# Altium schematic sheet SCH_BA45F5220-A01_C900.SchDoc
size A4; PageSetup: Record=PageOptions¦CenterHorizontal=True¦CenterVertical=True¦PrintScale=1.00¦XCorrection=1.00¦YCorrection=1.00¦PrintKind=1¦BorderSize=5000000¦LeftOffset=0¦BottomOffset=0¦Orientation=2¦PaperLength=1000¦PaperWidth=1000¦Scale=100¦PaperSource=7¦PrintQuality=-4¦MediaType=1¦DitherType=10¦PaperKind=A4¦PrintScaleMode=0
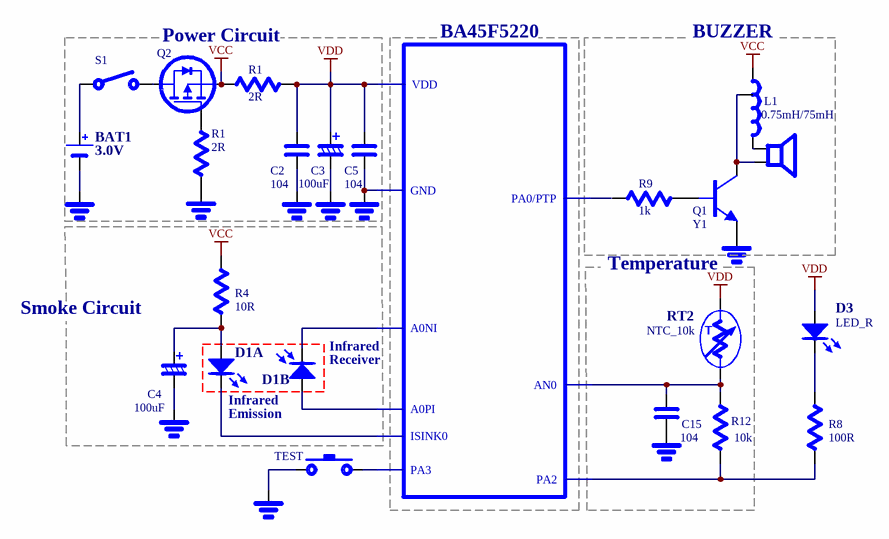
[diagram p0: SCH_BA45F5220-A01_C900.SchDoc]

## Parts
(Parts that share a designator on the sheet are numbered #1, #2 ... from top to bottom, then left to right.)
*  *  (value not drawn)
BAT1  3.0V  [CR2032]
C2  104
C3  100uF
C4  100uF
C5  104
C15  104
D1A  LED(1)  [LED3M]  (value not drawn)
D1B  *  [LED3M]  (value not drawn)
D3  LED_R  [LED3M]
GND1  GND(1)  (value not drawn)
GND2#1  GND(1)  (value not drawn)
GND2#2  GND(1)  (value not drawn)
GND2#3  GND(1)  (value not drawn)
GND3  GND(1)  (value not drawn)
GND4  GND(1)  (value not drawn)
GND7  GND(1)  (value not drawn)
GND8  GND(1)  (value not drawn)
GND9  GND(1)  (value not drawn)
L1  0.75mH/75mH
LS1  Speaker(1)  [PIN2]  (value not drawn)
Q1  Y1  [TO-226-AA]
Q2  PMOS  [TO-220AB]  (value not drawn)
R1#1  2R
R1#2  2R
R4  10R
R8  100R
R9  1k
R12  10k
RT2  NTC_10k
S1  SW(1)  (value not drawn)
TEST  SW(2)  (value not drawn)

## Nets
VCC: L1.1 Q2.3(S) R1#1.2 R4.1
VDD: *.VDD C2.1 C3.1 C5.1 D3.1(A) R1#1.1 RT2.2
Net*_47: *.47(A0NI) D1B.2(K)
Net*_48: *.48(A0PI) D1B.1(A)
Net*_49: *.49(ISINK0) D1A.2(K)
Net*_50: *.50(PA3) TEST.1
Net*_52: *.52(AN0) C15.1 R12.1 RT2.1
Net*_53: *.53(PA2) R8.2 R12.2
Net*_54: *.54(GND) C5.2 GND3.?1
NetBAT1_1: BAT1.1(+) S1.1
NetBAT1_2: BAT1.2(-) GND1.?1
NetC2_2: C2.2 GND2#2.?1
NetC3_2: C3.2 GND2#3.?1
NetC4_1: C4.1 D1A.1(A) R4.2
NetC4_2: C4.2 GND7.?1
NetC15_2: C15.2 GND9.?1
NetD3_2: D3.2(K) R8.1
NetGND2#1_?1: GND2#1.?1 R1#2.2
NetGND4_?1: GND4.?1 Q1.3(E)
NetGND8_?1: GND8.?1 TEST.2
NetL1_2: L1.2 LS1.1
NetL1_3: L1.3 LS1.2 Q1.1(C)
NetQ1_2: Q1.2(B) R9.1
NetQ2_1: Q2.1(G) R1#2.1
NetQ2_2: Q2.2(D) S1.2

Not connected (* = marked no-connect by the designer): * 51(PA0/PTP); R9 2

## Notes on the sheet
- Labels drawn without touching a wire or pin: BA45F5220, BUZZER, Emission, Infrared, Power Circuit, Receiver, Smoke Circuit, Temperature

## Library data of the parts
* = Component_1
BAT1 = Battery(1): Battery
C2 C5 C15 = Cap(1): Capacitor
C3 C4 = Cap(2): Capacitor
D1A D3 = LED(1): Typical INFRARED GaAs LED
D1B = Photo Diode(1): Photo Diode
GND1 GND2#1-GND2#3 GND3 GND4 GND7-GND9 = GND(1): GND
L1 = Incductor
LS1 = Speaker(1): Loudspeaker
Q1 = NPN(1): NPN Bipolar Transistor
Q2 = PMOS(2): P-Channel Power MOSFET; Note: Pin 2 is electrically connected to pin 4.
R1#1 R1#2 R4 R8 R9 R12 = Resistor(1): Resisitor
RT2 = TEMP
S1 = SW(1): Switch
TEST = SW(2): Switch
